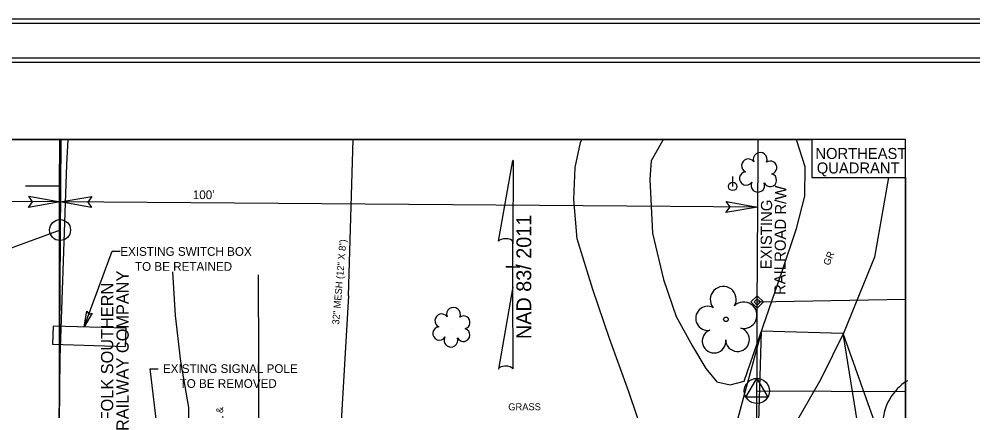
# Model space of a CAD drawing. Extents: x 1756964 to 1757438, y 736785 to 737067.
# Drawn here: x 1757129.6 to 1757266.4, y 737010.8 to 737067 of the extents above; entities that cross this region are included whole.
import ezdxf

# ---------------------------------------------------------------- set-up
doc = ezdxf.new("R2010")
doc.units = 0
for name, color, linetype in [('Exist Other Culture Fence Line', 7, 'Continuous'), ('Exist Other Culture Fence Line Text', 7, 'Continuous'), ('Exist Railroads Standard Gauge', 7, 'Continuous'), ('Exist Railroads Switch Box', 7, 'Continuous'), ('Exist Right of Way Line', 7, 'Continuous'), ('Exist Right of Way Line Text', 7, 'Continuous'), ('Exist Right of Way Width CELL', 7, 'Continuous'), ('Exist Roads Soil', 7, 'Continuous'), ('Exist Roads Soil Text', 7, 'Continuous'), ('Exist Utilities Power Pole CELL', 7, 'Continuous'), ('Exist Vegetation Shrub CELL', 7, 'Continuous'), ('Exist Vegetation Tree CELL', 7, 'Continuous'), ('Exist Vegetation Tree Text', 7, 'Continuous'), ('Old_Level_1', 7, 'Continuous'), ('Old_Level_18', 7, 'Continuous'), ('Old_Level_3', 7, 'Continuous'), ('Old_Level_62', 7, 'Continuous'), ('Old_Level_63', 7, 'Continuous'), ('Prop Dimension', 7, 'Continuous'), ('Prop Easement Permanent Drainage', 7, 'Continuous'), ('Prop Horizontal Alignment Tick Label', 7, 'Continuous'), ('Prop North Arrow NAD83 for Plan Sheets CELL', 7, 'Continuous'), ('Prop Plan Preparation Sketches Hydraulic Ditch', 7, 'Continuous'), ('Prop ROW Marker CELL', 7, 'Continuous'), ('Prop ROW Permanent Easement CELL', 7, 'Continuous'), ('Prop ROW RW Lines', 7, 'Continuous'), ('Prop SS Fill Line', 7, 'Continuous'), ('Prop Terminator CELL', 7, 'Continuous'), ('Sheet Block Revision CELL', 7, 'Continuous'), ('Sheet Plan CELL', 7, 'Continuous'), ('Sheet Plot Border Inside CELL', 7, 'Continuous'), ('Sheet Plot Border Outside CELL', 7, 'Continuous')]:
    doc.layers.add(name, color=color, linetype=linetype)

msp = doc.modelspace()

# ---------------------------------------------------------------- linework, layer by layer
at = {"layer": 'Exist Other Culture Fence Line'}
msp.add_line((1757176.84, 737027.28), (1757175.45, 737003.53), dxfattribs=at)
msp.add_lwpolyline([(1757176.84, 737027.28), (1757177.49, 737049.72)], dxfattribs=at)
at = {"layer": 'Exist Railroads Standard Gauge'}
for points in [[(1757135.24, 736995.21), (1757135.46, 737018.36), (1757136.42, 737046.14), (1757136.63, 737049.72)], [(1757135.39, 737011.34), (1757135.4, 737042.82), (1757135.43, 737049.72)]]:
    msp.add_lwpolyline(points, dxfattribs=at)
at = {"layer": 'Exist Railroads Switch Box'}
msp.add_lwpolyline([(1757144.94, 737022.63), (1757134.47, 737022.94), (1757134.39, 737020.32), (1757144.86, 737020.01)], close=True, dxfattribs=at)
at = {"layer": 'Exist Right of Way Line'}
msp.add_line((1757235.08, 736924.98), (1757235.47, 737036.37), dxfattribs=at)
msp.add_arc((1762390.7, 737018.29), 5155.26, 179.65064, 179.79908, dxfattribs=at)
at = {"layer": 'Exist Right of Way Width CELL'}
for p, q in [((1757135.49, 737040.75), (1757085.49, 737041.12)), ((1757235.49, 737040.02), (1757135.49, 737040.75))]:
    msp.add_line(p, q, dxfattribs=at)
for points in [[(1757131, 737041.56), (1757135.49, 737040.75), (1757130.96, 737039.98), (1757131.54, 737040.78)], [(1757139.98, 737039.94), (1757135.49, 737040.75), (1757140.02, 737041.52), (1757139.44, 737040.72)], [(1757230.99, 737040.83), (1757235.49, 737040.02), (1757230.96, 737039.25), (1757231.54, 737040.05)]]:
    msp.add_lwpolyline(points, close=True, dxfattribs=at)
at = {"layer": 'Exist Roads Soil'}
for points in [[(1757221.67, 736984.4), (1757222.07, 736986.66), (1757222.2, 736988.61), (1757222.21, 736991.57), (1757222.19, 736995.62), (1757221.81, 737000.37), (1757219.28, 737006.87), (1757217.03, 737013.5), (1757214.27, 737021.18), (1757211.87, 737028.19), (1757209.62, 737035.44), (1757209.12, 737041.12), (1757209.35, 737045.7), (1757210.1, 737049.28), (1757210.3, 737049.72)], [(1757222.04, 737049.72), (1757221.87, 737049.52), (1757220.23, 737046.63), (1757220.02, 737044.02), (1757220.44, 737036.28), (1757222.01, 737029.62), (1757223.84, 737024.33), (1757226.14, 737020.06), (1757228.05, 737016.85), (1757229.66, 737014.94), (1757231.57, 737014.49), (1757233.59, 737015.01), (1757238.9, 737030.51), (1757241.08, 737036.92), (1757242.26, 737041.59), (1757242.32, 737045.79), (1757241.12, 737049.54), (1757241.01, 737049.72)], [(1757254.26, 737044.26), (1757252.26, 737032.84), (1757247.84, 737022.03), (1757244.57, 737015.34), (1757240.29, 737007.91), (1757237.23, 737003.22), (1757236.16, 736998.79), (1757236.17, 736995.1), (1757235.79, 736991.16), (1757235.85, 736988.8), (1757237.48, 736985.93), (1757240.42, 736984.02)], [(1757150.96, 736990.77), (1757151.22, 736991.77), (1757151.56, 736992.22), (1757153.88, 736999.87), (1757154.04, 737004.02), (1757153.93, 737011.24), (1757152.81, 737017.85), (1757152.04, 737024.46), (1757151.66, 737030.74)], [(1757163.86, 737030.31), (1757163.91, 737018.1), (1757163.93, 737013.01), (1757163.96, 737006.58), (1757163.97, 737002.63), (1757164.34, 736998.44), (1757165.93, 736994.82), (1757167.47, 736992.71), (1757170.37, 736987.83)]]:
    msp.add_lwpolyline(points, dxfattribs=at)
at = {"layer": 'Exist Utilities Power Pole CELL'}
for q in [(1757231.92, 737044.4), (1757231.92, 737042.99)]:
    msp.add_line((1757231.92, 737042.99), q, dxfattribs=at)
msp.add_circle((1757231.92, 737042.99), 0.613, dxfattribs=at)
at = {"layer": 'Exist Vegetation Shrub CELL'}
for p, q in [((1757235.64, 737044.82), (1757235.64, 737044.82)), ((1757191.66, 737022.59), (1757191.66, 737022.59))]:
    msp.add_line(p, q, dxfattribs=at)
for centre, radius, start, end in [((1757234.16, 737045.95), 0.968, 35.8908, 245.4216), ((1757235.87, 737046.86), 0.99, 334.8391, 200.4717), ((1757237.32, 737045.69), 0.929, 284.4567, 126.0861), ((1757233.84, 737044.12), 0.955, 95.1099, 327.9534), ((1757237.28, 737043.89), 0.937, 204.9913, 73.4601), ((1757235.52, 737043.14), 0.984, 151.2797, 21.387), ((1757190.18, 737023.71), 0.968, 35.8908, 245.4216), ((1757191.89, 737024.63), 0.99, 334.8391, 200.4717), ((1757193.33, 737023.46), 0.929, 284.4567, 126.0861), ((1757189.86, 737021.88), 0.955, 95.1099, 327.9534), ((1757193.3, 737021.66), 0.937, 204.9913, 73.4601), ((1757191.53, 737020.9), 0.984, 151.2797, 21.387)]:
    msp.add_arc(centre, radius, start, end, dxfattribs=at)
at = {"layer": 'Exist Vegetation Tree CELL'}
msp.add_line((1757230.95, 737023.9), (1757230.95, 737023.9), dxfattribs=at)
msp.add_circle((1757230.95, 737023.9), 0.326, dxfattribs=at)
for centre, radius, start, end in [((1757230.57, 737026.77), 1.86, 330.1651, 219.7134), ((1757233.5, 737024.49), 1.9, 257.1011, 134.1999), ((1757228.35, 737024.05), 1.73, 62.6636, 279.3457), ((1757229.25, 737020.78), 1.69, 111.5671, 6.231), ((1757232.62, 737021), 1.7, 181.2822, 74.56)]:
    msp.add_arc(centre, radius, start, end, dxfattribs=at)
at = {"layer": 'Old_Level_1'}
for p, q in [((1757235.37, 736998.42), (1757236.06, 737022.22)), ((1757247.77, 737021.88), (1757236.06, 737022.22)), ((1757251.67, 736997.63), (1757247.77, 737021.88))]:
    msp.add_line(p, q, dxfattribs=at)
at = {"layer": 'Old_Level_18'}
msp.add_lwpolyline([(1757032.86, 737049.72), (1757243.29, 737049.72), (1757243.29, 737044.26), (1757256.72, 737044.26), (1757256.72, 736930.25), (1757242.38, 736930.25), (1757242.38, 736924.98), (1757033.35, 736924.98), (1757033.35, 736930.17), (1757018.66, 736930.17), (1757018.66, 737044.64), (1757032.53, 737044.64)], close=True, dxfattribs=at)
at = {"layer": 'Old_Level_3'}
msp.add_line((1757135.47, 737036.72), (1757122.27, 737031.82), dxfattribs=at)
msp.add_circle((1757135.47, 737036.72), 1.5, dxfattribs=at)
at = {"layer": 'Old_Level_62'}
msp.add_lwpolyline([(1756969.89, 736798.25), (1757382.39, 736798.25), (1757382.39, 737060.75), (1756969.89, 737060.75)], close=True, dxfattribs=at)
at = {"layer": 'Old_Level_63'}
msp.add_lwpolyline([(1757388.64, 737067), (1756963.64, 737067), (1756963.64, 736792), (1757388.64, 736792)], close=True, dxfattribs=at)
at = {"layer": 'Prop Dimension'}
for p, q in [((1757138.91, 737022.82), (1757142.96, 737033.68)), ((1757142.96, 737033.68), (1757144.07, 737033.68)), ((1757148.41, 737016.82), (1757149.52, 737016.82)), ((1757150.3, 737000.64), (1757148.41, 737016.82))]:
    msp.add_line(p, q, dxfattribs=at)
at = {"layer": 'Prop Easement Permanent Drainage'}
msp.add_line((1757235.44, 737026.4), (1757256.72, 737026.79), dxfattribs=at)
at = {"layer": 'Prop Horizontal Alignment Tick Label'}
msp.add_line((1757135.08, 736924.98), (1757135.47, 737036.72), dxfattribs=at)
msp.add_arc((1762390.7, 737018.29), 5255.26, 179.65729, 179.79908, dxfattribs=at)
at = {"layer": 'Prop North Arrow NAD83 for Plan Sheets CELL'}
for p, q in [((1757198.35, 737035.11), (1757200.4, 737046.7)), ((1757200.42, 737046.7), (1757200.4, 737046.7)), ((1757200.42, 737046.7), (1757200.4, 737046.7)), ((1757200.42, 737046.7), (1757200.41, 737034.75)), ((1757200.41, 737028.55), (1757200.41, 737035.1)), ((1757200.41, 737034.75), (1757200.41, 737035.09)), ((1757199.41, 737031.45), (1757199.4, 737031.45)), ((1757200.3, 737031.45), (1757199.41, 737031.45)), ((1757199.42, 737031.45), (1757201.42, 737031.45)), ((1757200.41, 737028.55), (1757198.32, 737016.74)), ((1757200.42, 737016.79), (1757200.41, 737028.55))]:
    msp.add_line(p, q, dxfattribs=at)
for centre, start_param, end_param in [((1757199.38, 737034.99), 0.216388, 2.908219), ((1757199.37, 737016.7), 0.201328, 3.141593)]:
    msp.add_ellipse(centre, major_axis=(1.06, -0.01), ratio=0.461098, start_param=start_param, end_param=end_param, dxfattribs=at)
at = {"layer": 'Prop Plan Preparation Sketches Hydraulic Ditch'}
msp.add_arc((1757260.99, 737008.69), 7.57, 122.0708, 235.6218, dxfattribs=at)
at = {"layer": 'Prop ROW Marker CELL'}
for p, q in [((1757235.44, 737026.4), (1757235.44, 737026.4)), ((1757235.39, 737013.63), (1757235.39, 737013.63))]:
    msp.add_line(p, q, dxfattribs=at)
msp.add_lwpolyline([(1757233.83, 737012.73), (1757235.39, 737015.43), (1757236.96, 737012.73)], close=True, dxfattribs=at)
msp.add_circle((1757235.39, 737013.63), 1.8, dxfattribs=at)
at = {"layer": 'Prop ROW Permanent Easement CELL'}
for points in [[(1757234.54, 737026.4), (1757235.44, 737027.3), (1757236.34, 737026.4), (1757235.44, 737025.5)], [(1757234.99, 737026.4), (1757235.44, 737026.85), (1757235.89, 737026.4), (1757235.44, 737025.95)]]:
    msp.add_lwpolyline(points, close=True, dxfattribs=at)
at = {"layer": 'Prop ROW RW Lines'}
msp.add_line((1757235.39, 737013.63), (1757256.72, 737013.54), dxfattribs=at)
at = {"layer": 'Prop SS Fill Line'}
for p, q in [((1757236.06, 737022.22), (1757232.01, 737007.34)), ((1757255.22, 737000.9), (1757247.77, 737021.88))]:
    msp.add_line(p, q, dxfattribs=at)
at = {"layer": 'Prop Terminator CELL'}
msp.add_lwpolyline([(1757140.07, 737024.79), (1757138.91, 737022.82), (1757139.33, 737025.08), (1757139.61, 737024.67)], close=True, dxfattribs=at)
at = {"layer": 'Sheet Block Revision CELL'}
msp.add_line((1757135.5, 737043), (1757130.5, 737043.02), dxfattribs=at)
at = {"layer": 'Sheet Plan CELL'}
msp.add_line((1757135.24, 736995.21), (1757135.64, 737049.72), dxfattribs=at)
for points in [[(1757382.4, 737060.75), (1757007.39, 737060.75), (1757007.39, 736798.25), (1757382.39, 736798.25)], [(1757256.72, 737049.72), (1757018.66, 737049.72), (1757018.66, 736924.98), (1757256.72, 736924.98)]]:
    msp.add_lwpolyline(points, close=True, dxfattribs=at)
at = {"layer": 'Sheet Plot Border Inside CELL'}
msp.add_lwpolyline([(1756969.02, 736797.62), (1757385.52, 736797.62), (1757385.52, 737061.37), (1756969.02, 737061.37)], close=True, dxfattribs=at)
at = {"layer": 'Sheet Plot Border Outside CELL'}
msp.add_lwpolyline([(1756965.77, 736792.62), (1757386.64, 736792.62), (1757386.64, 737066.37), (1756965.77, 737066.37)], close=True, dxfattribs=at)

# ---------------------------------------------------------------- texts
at = {"layer": 'Exist Other Culture Fence Line Text'}
msp.add_text('32" MESH (12" X 8")', height=1, rotation=84.9713, dxfattribs=at).set_placement((1757175.47, 737023.12))
at = {"layer": 'Exist Right of Way Line Text'}
for s, p in [('RAILROAD R/W', (1757239.48, 737027.39)), ('EXISTING ', (1757237.5, 737031.09))]:
    msp.add_text(s, height=1.6, rotation=89.5215, dxfattribs=at).set_placement(p)
at = {"layer": 'Exist Right of Way Width CELL'}
msp.add_text("100'", height=1.25, rotation=360, dxfattribs=at).set_placement((1757154.5, 737041.16))
at = {"layer": 'Exist Roads Soil Text'}
for s, rotation, p in [('GR', 67.77, (1757245.78, 737031.55)), ('SOIL &', 90.2226, (1757158.87, 737007.03))]:
    msp.add_text(s, height=1, rotation=rotation, dxfattribs=at).set_placement(p)
at = {"layer": 'Exist Vegetation Tree Text'}
msp.add_text('GRASS', height=1, rotation=0.3497, dxfattribs=at).set_placement((1757199.74, 737010.84))
at = {"layer": 'Old_Level_3'}
for s, p in [('RAILWAY COMPANY', (1757145.31, 737007.88)), ('NORTHFOLK SOUTHERN', (1757143.09, 737000.94))]:
    msp.add_text(s, height=1.75, rotation=90, dxfattribs=at).set_placement(p)
at = {"layer": 'Prop Dimension'}
for s, p in [('EXISTING SWITCH BOX', (1757144.1, 737033.02)), ('TO BE RETAINED', (1757146.21, 737030.87)), ('EXISTING SIGNAL POLE', (1757150.22, 737016.21)), ('TO BE REMOVED', (1757152.61, 737014.07))]:
    msp.add_text(s, height=1.25, rotation=360, dxfattribs=at).set_placement(p)
at = {"layer": 'Prop North Arrow NAD83 for Plan Sheets CELL'}
msp.add_text('NAD 83/ 2011', height=2.125, rotation=89.9761, dxfattribs=at).set_placement((1757203.03, 737021.07))
at = {"layer": 'Sheet Plan CELL'}
for s, p in [('NORTHEAST', (1757243.78, 737046.92)), ('QUADRANT', (1757243.98, 737044.84))]:
    msp.add_text(s, height=1.582, rotation=360, dxfattribs=at).set_placement(p)

doc.saveas('drawing.dxf')
